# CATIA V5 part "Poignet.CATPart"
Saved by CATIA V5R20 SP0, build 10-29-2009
Part number: Poignet
Bounding box of the stored display mesh (mm): x -7.91 to 102.199, y 29.075 to 53.325, z -23.029 to 1.029
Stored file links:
  E:\Boulot\SeaTech\2eme ANNEE\FabricationAdditive\TP_MOSM_CREM\Projet Sauterelle de serrage\CAO Assemblage Sauterelle\Poignet.CATPart
  E:\Boulot\SeaTech\2eme ANNEE\FabricationAdditive\TP_MOSM_CREM\Projet Sauterelle de serrage\CAO Sauterelle ORIGINE 4\Sauterelle_horizontale_05120-06.CATPart
  E:\Boulot\SeaTech\2eme ANNEE\FabricationAdditive\TP_MOSM_CREM\Projet Sauterelle de serrage\CAO Assemblage Sauterelle\Sauterelle_horizontale_05120-06.CATPart
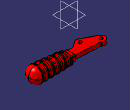
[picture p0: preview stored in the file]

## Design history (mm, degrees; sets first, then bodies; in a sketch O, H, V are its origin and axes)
Body1 (main body)
  Solid1 "05120-06_5": solid without history
Body2
  Solid2 "05120-06_15": solid without history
